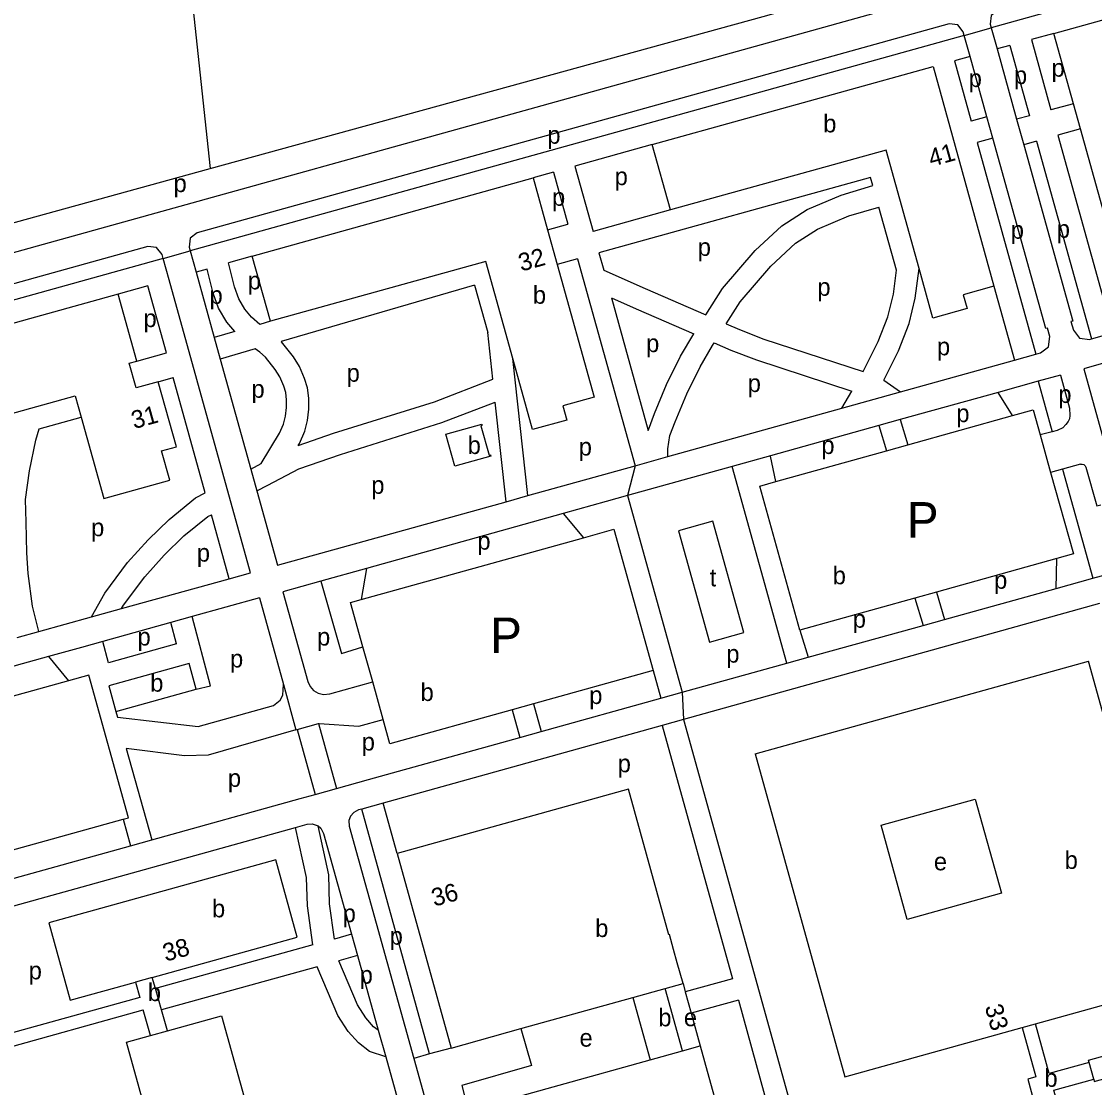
# Model space of a CAD drawing. Extents: x 158358 to 160383, y 379531 to 380764.
# Drawn here: x 159782.3 to 160024.2, y 380334.2 to 380574.3 of the extents above; entities that cross this region are included whole.
import ezdxf

# ---------------------------------------------------------------- set-up
doc = ezdxf.new("R2010")
doc.units = 0
for name, color, linetype in [('BLT_Basislijn', 7, 'Continuous'), ('BLT_Bebouwing', 7, 'Continuous'), ('BLT_Centroide', 7, 'Continuous'), ('BLT_Huisnummer', 7, 'Continuous'), ('BLT_Huisnummer_reeks', 7, 'Continuous'), ('BLT_Onderverdeling_panden', 7, 'Continuous'), ('BLT_Tekst_parkeren', 7, 'Continuous'), ('BLT_Vlakafsluiter', 7, 'Continuous')]:
    doc.layers.add(name, color=color, linetype=linetype)

msp = doc.modelspace()

# ---------------------------------------------------------------- linework, layer by layer
at = {"layer": 'BLT_Basislijn'}
for p, q in [((160019.45, 380555.77), (160014.34, 380554.39)), ((159999.92, 380552.86), (159996.4, 380551.89)), ((160009.51, 380553.09), (160006.62, 380552.32)), ((160021.02, 380550.12), (160015.93, 380548.69)), ((160001.26, 380548.05), (159997.73, 380547.07)), ((160011.11, 380547.33), (160008.23, 380546.52)), ((159902.25, 380540.36), (159905.49, 380528.69)), ((159907.07, 380541.71), (159911.15, 380527)), ((159928.62, 380531.85), (159911.15, 380527)), ((159900.88, 380527.41), (159905.49, 380528.69)), ((159912.48, 380522.19), (159913.57, 380518.27)), ((159907.67, 380520.85), (159920.6, 380474.22)), ((159884.45, 380514.89), (159840.82, 380502.26)), ((160001.52, 380514.71), (160006.16, 380498.01)), ((159915.29, 380512.06), (159923.59, 380482.15)), ((159838.46, 380506.78), (159836.06, 380506.08)), ((159830.39, 380504.44), (159825.74, 380503.1)), ((159888.54, 380493.7), (159887.4, 380504.22)), ((159808.28, 380497.8), (159814.96, 380499.67)), ((159835.01, 380500.57), (159827.08, 380498.28)), ((159896.41, 380467.5), (159893.06, 380498.43)), ((159813.13, 380493.16), (159816.51, 380494.1)), ((160005.7, 380485.55), (160002.44, 380490.76)), ((159891.53, 380466.14), (159889.1, 380488.56)), ((159975.59, 380483.29), (159977.26, 380477.62)), ((159980.4, 380484.63), (159982.08, 380478.96)), ((160014.64, 380481.89), (160011.94, 380481.16)), ((160015.78, 380482.21), (160014.64, 380481.89)), ((159952.38, 380470.67), (159951.13, 380476.36)), ((160016.98, 380473.47), (160014.29, 380472.73)), ((160021.01, 380474.58), (160016.98, 380473.47)), ((159918.9, 380467.52), (159931.22, 380423.2)), ((159904.41, 380463.48), (159908.96, 380458.01)), ((160015.55, 380446.6), (160015.72, 380453.35)), ((159860.05, 380451.09), (159858.84, 380444.08)), ((159983.71, 380444.42), (159985.53, 380438.27)), ((159988.53, 380445.77), (159990.35, 380439.61)), ((159957.78, 380437.19), (159959.65, 380431.09)), ((159788.36, 380431.24), (159792.9, 380425.76)), ((159924.67, 380428.11), (159926.4, 380421.86)), ((159897.69, 380420.61), (159899.45, 380414.37)), ((159803.6, 380418.88), (159803.97, 380417.56)), ((159892.88, 380419.27), (159894.63, 380413.03)), ((159931.55, 380417.09), (159964.23, 380299.3)), ((159844.46, 380414.81), (159848.51, 380400.21)), ((159849.28, 380416.16), (159853.32, 380401.55)), ((159926.73, 380415.75), (159942.56, 380358.68)), ((159805.92, 380410.57), (159811.68, 380389.98)), ((159866.96, 380386.87), (159863.8, 380398.24)), ((159805.2, 380394.59), (159806.87, 380388.64)), ((159856.72, 380368.69), (159852.83, 380367.61)), ((159847.96, 380366.27), (159812.51, 380356.46)), ((159858.06, 380363.87), (159853.83, 380362.7)), ((159848.97, 380361.36), (159813.87, 380351.65)), ((159931.43, 380357.59), (159931.94, 380355.74)), ((159942.56, 380358.68), (159931.94, 380355.74)), ((159931.94, 380355.74), (159933.28, 380350.92)), ((159943.9, 380353.87), (159933.28, 380350.92)), ((159943.9, 380353.87), (159956.78, 380307.42)), ((159933.28, 380350.92), (159935.32, 380343.57)), ((159879.13, 380343.06), (159874.31, 380341.72)), ((159874.31, 380341.72), (159870.73, 380340.69))]:
    msp.add_line(p, q, dxfattribs=at)
for points in [[(159789.02, 380665.27), (159793.46, 380660.92), (159804.18, 380646.64), (159811.39, 380635.41), (159815.6, 380624.35), (159817.77, 380612.72), (159819.82, 380588.21), (159824.85, 380541.18)], [(160152.18, 380625.57), (159545.87, 380457.04)], [(160140.65, 380615.31), (160002.48, 380576.9), (160000.91, 380575.68), (160000.67, 380573.7)], [(160141.65, 380612.04), (160000.9, 380572.88)], [(159824.85, 380541.18), (159949.46, 380575.46), (160033.92, 380599.61), (160042.54, 380602.05)], [(159994.6, 380572.01), (159993.38, 380573.58), (159991.4, 380573.82), (159821.88, 380526.7), (159820.31, 380525.47), (159820.07, 380523.5)], [(159994.83, 380571.19), (159994.6, 380572.01)], [(160000.67, 380573.7), (160000.9, 380572.88)], [(160000.9, 380572.88), (160002.22, 380568.14)], [(159994.83, 380571.19), (159820.31, 380522.63)], [(159996.15, 380566.45), (159994.83, 380571.19)], [(160015.04, 380571.62), (160009.94, 380570.24)], [(160009.94, 380570.24), (160014.34, 380554.39)], [(160005.11, 380568.92), (160002.22, 380568.14)], [(160002.22, 380568.14), (160006.62, 380552.32)], [(160005.11, 380568.92), (160009.51, 380553.09)], [(159996.15, 380566.45), (159992.63, 380565.48)], [(159992.63, 380565.48), (159996.4, 380551.89)], [(159999.92, 380552.86), (159996.15, 380566.45)], [(160001.26, 380548.05), (159999.92, 380552.86)], [(160006.62, 380552.32), (160008.23, 380546.52)], [(160010.98, 380499.34), (160012.02, 380499.64), (160013.83, 380501.05), (160014.11, 380503.33), (160013.57, 380505.26), (160013.19, 380505.15), (160001.26, 380548.05)], [(160015.93, 380548.69), (160028.3, 380504.16)], [(159924.5, 380546.57), (159907.07, 380541.71)], [(159997.73, 380547.07), (160010.98, 380499.34)], [(160008.23, 380546.52), (160019.26, 380506.84), (160018.87, 380506.73), (160019.41, 380504.8), (160020.82, 380502.99), (160023.1, 380502.71), (160023.49, 380502.82)], [(160011.11, 380547.33), (160023.49, 380502.82)], [(159748.71, 380520.22), (159824.85, 380541.18)], [(159902.25, 380540.36), (159897.64, 380539.08)], [(159974.24, 380537.33), (159973.72, 380539.18), (159912.48, 380522.19)], [(159936.54, 380508.23), (159940.31, 380514.16), (159947.65, 380522.7), (159953.71, 380528.31), (159959.38, 380531.99), (159967.11, 380535.22), (159974.24, 380537.33)], [(159941.18, 380506.2), (159944.34, 380511.18), (159951.25, 380519.22), (159956.79, 380524.35), (159961.72, 380527.55), (159968.79, 380530.51), (159975.58, 380532.52)], [(159979.54, 380518.27), (159975.58, 380532.52)], [(159814, 380521.81), (159812.77, 380523.38), (159810.8, 380523.62), (159592.76, 380463.02), (159590.81, 380462.27), (159589.15, 380461.15), (159588.02, 380459.94), (159587.63, 380459.39)], [(159820.07, 380523.5), (159820.31, 380522.63)], [(159814.24, 380520.94), (159814, 380521.81)], [(159820.31, 380522.63), (159821.65, 380517.81)], [(159834.31, 380521.48), (159828.96, 380519.93)], [(159814.24, 380520.94), (159586.57, 380457.59)], [(159815.58, 380516.12), (159814.24, 380520.94)], [(159836.06, 380506.08), (159834.19, 380507.69), (159832.67, 380509.48), (159831.28, 380511.86), (159830.33, 380514.55), (159828.96, 380519.93)], [(159907.67, 380520.85), (159903.05, 380519.57)], [(159976.66, 380493.51), (159979.98, 380500.15), (159982.39, 380506.3), (159983.77, 380511.99), (159984.63, 380518.64)], [(159824.15, 380518.54), (159821.65, 380517.81)], [(159821.65, 380517.81), (159825.74, 380503.1)], [(159830.39, 380504.44), (159828.58, 380506.58), (159826.72, 380509.74), (159825.54, 380513.1), (159824.15, 380518.54)], [(159913.57, 380518.27), (159922.91, 380514.19), (159936.54, 380508.23)], [(159972.06, 380495.49), (159972.11, 380495.58), (159975.41, 380502.19), (159977.62, 380507.81), (159978.85, 380512.9), (159979.54, 380518.27)], [(159810.76, 380514.78), (159804.07, 380512.92)], [(159814.96, 380499.67), (159810.76, 380514.78)], [(159833.92, 380450.13), (159815.58, 380516.12)], [(159884.45, 380514.89), (159887.4, 380504.22)], [(159915.29, 380512.06), (159920.9, 380509.61), (159933.83, 380503.96)], [(159941.18, 380506.2), (159944.14, 380504.91), (159949.65, 380502.78), (159972.06, 380495.49)], [(160023.49, 380502.82), (160028.3, 380504.16)], [(159825.74, 380503.1), (159827.08, 380498.28)], [(159844.66, 380478.79), (159844.95, 380479.26), (159846.15, 380482.03), (159846.74, 380484.45), (159847.08, 380487.01), (159847.06, 380489.44), (159846.76, 380491.77), (159846.13, 380493.87), (159844.98, 380496.56), (159843.61, 380498.79), (159840.95, 380502.14), (159840.82, 380502.26)], [(159923.59, 380482.15), (159923.62, 380482.36), (159924.98, 380485.98), (159927.71, 380492.51), (159930.87, 380498.89), (159933.83, 380503.96)], [(159928.03, 380476.29), (159927.97, 380478.02), (159928.48, 380481.06), (159929.63, 380484.14), (159932.26, 380490.44), (159935.27, 380496.51), (159938.07, 380501.32), (159938.47, 380501.93)], [(159938.47, 380501.93), (159942.23, 380500.29), (159947.97, 380498.06), (159969.49, 380491.07)], [(159836.32, 380474.71), (159840.5, 380481.57), (159841.39, 380483.62), (159841.82, 380485.37), (159842.08, 380487.32), (159842.06, 380489.1), (159841.86, 380490.72), (159841.42, 380492.15), (159840.52, 380494.26), (159839.51, 380495.92), (159837.31, 380498.68), (159836.05, 380499.79), (159835.01, 380500.57)], [(160006.16, 380498.01), (160010.98, 380499.34)], [(159827.08, 380498.28), (159833.97, 380473.48)], [(159980.47, 380490.87), (160006.16, 380498.01)], [(160028.8, 380498.07), (160021.81, 380496.07)], [(160016.49, 380494.66), (160011.47, 380493.27)], [(160016.49, 380494.66), (160018.58, 380487.18), (160018.65, 380485.56), (160018.51, 380484.83), (160018.24, 380484.21), (160017.75, 380483.49), (160017.01, 380482.81), (160015.78, 380482.21)], [(160021.81, 380496.07), (160027.37, 380476.05), (160027.97, 380474.83), (160028.49, 380474.26), (160029.15, 380473.74), (160029.64, 380473.49), (160030.2, 380473.3), (160030.98, 380473.15), (160032.36, 380473.3), (160060.95, 380481.22)], [(159823.73, 380468.14), (159816.51, 380494.1)], [(159844.66, 380478.79), (159852.67, 380481.54), (159875.42, 380488.66), (159888.54, 380493.7)], [(159976.66, 380493.51), (159980.47, 380490.87)], [(160011.47, 380493.27), (160002.44, 380490.76)], [(160011.47, 380493.27), (160014.64, 380481.89)], [(159967.25, 380487.19), (159969.49, 380491.07)], [(159967.25, 380487.19), (159980.47, 380490.87)], [(160002.44, 380490.76), (159980.4, 380484.63)], [(159835.34, 380468.56), (159837.84, 380469.86), (159844.86, 380473.57), (159854.23, 380476.79), (159877.06, 380483.94), (159889.1, 380488.56)], [(159928.03, 380476.29), (159967.25, 380487.19)], [(159786.28, 380482.56), (159795.74, 380485.19)], [(159786.18, 380436.86), (159784.81, 380442.59), (159783.8, 380449.97), (159783.49, 380454.65), (159783.33, 380461.52), (159783.24, 380466.64), (159784.08, 380473.1), (159785.51, 380479.98), (159786.28, 380482.56)], [(159975.59, 380483.29), (159951.11, 380476.48)], [(159980.4, 380484.63), (159975.59, 380483.29)], [(159920.6, 380474.22), (159928.03, 380476.29)], [(159951.11, 380476.48), (159942.51, 380474.09)], [(159833.97, 380473.48), (159836.32, 380474.71)], [(159833.97, 380473.48), (159835.34, 380468.56)], [(159896.41, 380467.5), (159920.6, 380474.22)], [(159942.51, 380474.09), (159918.9, 380467.52)], [(159954.83, 380429.75), (159942.51, 380474.09)], [(160016.98, 380473.47), (160023.81, 380448.89)], [(160021.01, 380474.58), (160021.43, 380474.61), (160021.79, 380474.49), (160022.09, 380474.23), (160022.25, 380473.9), (160024.68, 380465.19), (160025.57, 380465.43)], [(159798.12, 380440.18), (159801.08, 380445.56), (159806.22, 380452.41), (159810.87, 380457.55), (159815.6, 380462.15), (159821.54, 380467), (159823.73, 380468.14)], [(159835.34, 380468.56), (159839.99, 380451.82)], [(159839.99, 380451.82), (159891.53, 380466.14)], [(159891.53, 380466.14), (159896.41, 380467.5)], [(159914.08, 380466.18), (159904.41, 380463.48)], [(159918.9, 380467.52), (159914.08, 380466.18)], [(159804.85, 380442.05), (159805.29, 380442.84), (159810.08, 380449.22), (159814.47, 380454.08), (159818.93, 380458.41), (159824.31, 380462.8), (159825.1, 380463.21)], [(159829.11, 380448.79), (159825.1, 380463.21)], [(159904.41, 380463.48), (159860.05, 380451.09)], [(159860.05, 380451.09), (159849.78, 380448.22)], [(159804.85, 380442.05), (159829.11, 380448.79)], [(159829.11, 380448.79), (159833.92, 380450.13)], [(160015.55, 380446.6), (160023.81, 380448.89)], [(160023.81, 380448.89), (160029.69, 380450.52)], [(159849.78, 380448.22), (159841.24, 380445.83)], [(159849.78, 380448.22), (159854.45, 380431.97), (159859.27, 380433.44)], [(159990.35, 380439.61), (160015.55, 380446.6)], [(159835.92, 380444.47), (159820.81, 380440.26)], [(159835.92, 380444.47), (159841.33, 380424.94)], [(159841.24, 380445.83), (159846.84, 380425.64), (159847.34, 380424.53), (159848.16, 380423.62), (159849.2, 380423), (159850.38, 380422.7), (159851.78, 380422.85), (159861.47, 380425.54)], [(159798.12, 380440.18), (159804.85, 380442.05)], [(160025.27, 380443.18), (159931.55, 380417.09)], [(159786.18, 380436.86), (159798.12, 380440.18)], [(159815.99, 380438.92), (159800.66, 380434.66)], [(159820.81, 380440.26), (159815.99, 380438.92)], [(159817.27, 380434.09), (159815.99, 380438.92)], [(159821.67, 380423.9), (159824.93, 380424.65), (159820.81, 380440.26)], [(159985.53, 380438.27), (159990.35, 380439.61)], [(159781.36, 380435.52), (159786.18, 380436.86)], [(159959.65, 380431.09), (159985.53, 380438.27)], [(159800.66, 380434.66), (159795.84, 380433.32)], [(159801.94, 380429.81), (159800.66, 380434.66)], [(159817.27, 380434.09), (159801.94, 380429.81)], [(159795.84, 380433.32), (159788.36, 380431.24)], [(159788.36, 380431.24), (159707.73, 380408.83)], [(159931.22, 380423.2), (159954.83, 380429.75)], [(159954.83, 380429.75), (159959.65, 380431.09)], [(159803.97, 380417.56), (159822.14, 380415.49), (159839.08, 380420.24), (159840.61, 380421.4), (159841.22, 380422.54), (159841.33, 380424.94)], [(159841.33, 380424.94), (159844.17, 380414.72)], [(159899.45, 380414.37), (159926.4, 380421.86)], [(159926.4, 380421.86), (159931.22, 380423.2)], [(159849.28, 380416.16), (159849.39, 380416.19), (159858.33, 380415.59), (159863.81, 380417.09)], [(159931.55, 380417.09), (159926.73, 380415.75)], [(159844.17, 380414.72), (159824.37, 380409.04), (159819.03, 380408.88), (159805.92, 380410.57)], [(159844.17, 380414.72), (159844.46, 380414.81)], [(159844.46, 380414.81), (159849.28, 380416.16)], [(159926.73, 380415.75), (159863.8, 380398.24)], [(159860.52, 380403.55), (159894.63, 380413.03)], [(159894.63, 380413.03), (159899.45, 380414.37)], [(159853.32, 380401.55), (159860.52, 380403.55)], [(159845.09, 380399.26), (159848.51, 380400.21)], [(159848.51, 380400.21), (159853.32, 380401.55)], [(159811.68, 380389.98), (159845.09, 380399.26)], [(159863.8, 380398.24), (159858.99, 380396.9)], [(159858.99, 380396.9), (159858.27, 380396.7), (159857.22, 380396.13), (159856.46, 380395.28), (159856.11, 380394.31), (159856.19, 380393.01), (159870.73, 380340.69)], [(159874.31, 380341.72), (159858.99, 380396.9)], [(159844.1, 380392.76), (159846.71, 380393.49), (159847.84, 380393.56), (159848.99, 380393.21), (159849.15, 380393.08)], [(159849.15, 380393.08), (159849.77, 380392.57), (159850.41, 380391.4), (159856.72, 380368.69)], [(159852.83, 380367.61), (159851.77, 380375.51), (159851.55, 380382.1), (159849.15, 380393.08)], [(159779.25, 380374.73), (159844.1, 380392.76)], [(159847.96, 380366.27), (159846.79, 380375.09), (159846.57, 380381.47), (159844.1, 380392.76)], [(159720.05, 380364.51), (159806.87, 380388.64)], [(159806.87, 380388.64), (159811.68, 380389.98)], [(159856.72, 380368.69), (159858.06, 380363.87)], [(159858.06, 380363.87), (159862.73, 380347.08)], [(159864.4, 380341.04), (159860.78, 380342.28), (159858.26, 380344.2), (159855.96, 380346.82), (159853.59, 380350.38), (159848.97, 380361.36)], [(159862.73, 380347.08), (159861.69, 380347.87), (159859.94, 380349.87), (159858.01, 380352.76), (159853.83, 380362.7)], [(160022.94, 380339.83), (160022.8, 380340.34), (160056.55, 380349.72)], [(159862.73, 380347.08), (159864.4, 380341.04)], [(159894.88, 380347.44), (159897.28, 380339.12), (159881.55, 380334.6), (159883.03, 380328.99)], [(160024, 380336.04), (160024.14, 380335.53), (160057.89, 380344.91)], [(159864.4, 380341.04), (159877.04, 380295.57)], [(159870.73, 380340.69), (159874.63, 380326.66)]]:
    msp.add_lwpolyline(points, dxfattribs=at)
msp.add_lwpolyline([(159930.41, 380459.57), (159937.4, 380434.52), (159945.12, 380436.64), (159938.13, 380461.72)], close=True, dxfattribs=at)
at = {"layer": 'BLT_Bebouwing'}
for p, q in [((159982.08, 380478.96), (160005.7, 380485.55)), ((160011.94, 380481.16), (160014.29, 380472.73)), ((159952.38, 380470.67), (159977.26, 380477.62)), ((159977.26, 380477.62), (159982.08, 380478.96)), ((160015.72, 380453.35), (159988.53, 380445.77)), ((159983.71, 380444.42), (159957.78, 380437.19)), ((159988.53, 380445.77), (159983.71, 380444.42)), ((159930.13, 380362.28), (159929.3, 380365.26)), ((159812.51, 380356.46), (159811.79, 380358.97)), ((159813.87, 380351.65), (159812.51, 380356.46)), ((159920.12, 380354.45), (159924.03, 380340.42)), ((159931.3, 380342.45), (159927.39, 380356.47)), ((159775.8, 380342.21), (159809.75, 380351.7)), ((159815.22, 380346.91), (159813.87, 380351.65)), ((159937.28, 380336.53), (159939.47, 380328.65))]:
    msp.add_line(p, q, dxfattribs=at)
for points in [[(160015.04, 380571.62), (160070.73, 380587.12)], [(160019.45, 380555.77), (160015.04, 380571.62)], [(159924.5, 380546.57), (159987.81, 380564.15)], [(159987.81, 380564.15), (160001.52, 380514.71)], [(160021.02, 380550.12), (160019.45, 380555.77)], [(160040.01, 380544.56), (160046.95, 380519.63), (160030.76, 380515.13), (160021.02, 380550.12)], [(159928.62, 380531.85), (159924.5, 380546.57)], [(159984.63, 380518.64), (159977.2, 380545.33), (159928.62, 380531.85)], [(159834.31, 380521.48), (159897.64, 380539.08)], [(159897.64, 380539.08), (159900.88, 380527.41)], [(159900.88, 380527.41), (159903.05, 380519.57)], [(159838.46, 380506.78), (159834.31, 380521.48)], [(159893.06, 380498.43), (159886.99, 380520.25), (159838.46, 380506.78)], [(159903.05, 380519.57), (159911.36, 380489.66), (159904.36, 380487.7), (159905.24, 380484.53), (159897.53, 380482.38), (159893.06, 380498.43)], [(160001.52, 380514.71), (159994.58, 380512.76), (159995.45, 380509.64), (159987.73, 380507.49), (159984.63, 380518.64)], [(159804.07, 380512.92), (159737.61, 380494.43)], [(159808.28, 380497.8), (159804.07, 380512.92)], [(159813.13, 380493.16), (159808.13, 380491.76), (159806.59, 380497.33), (159808.28, 380497.8)], [(159737.61, 380494.43), (159741.68, 380479.78), (159744.9, 380480.68), (159746.05, 380476.57), (159794.4, 380490.01), (159795.74, 380485.19)], [(159795.74, 380485.19), (159800.84, 380466.88), (159815.72, 380471.02), (159813.9, 380477.57), (159817.21, 380478.49), (159813.13, 380493.16)], [(160005.7, 380485.55), (160010.35, 380486.85), (160011.94, 380481.16)], [(159879.97, 380474.16), (159877.97, 380481.35), (159886.09, 380483.61), (159886.17, 380483.34), (159885.88, 380483.26), (159887.73, 380476.61), (159888.01, 380476.69), (159888.09, 380476.42), (159879.97, 380474.16)], [(160014.29, 380472.73), (160019.42, 380454.38), (160015.72, 380453.35)], [(159957.78, 380437.19), (159948.73, 380469.65), (159952.38, 380470.67)], [(159908.96, 380458.01), (159915.82, 380459.92), (159924.67, 380428.11)], [(159858.84, 380444.08), (159908.96, 380458.01)], [(159859.27, 380433.44), (159856.49, 380443.43), (159858.84, 380444.08)], [(159861.47, 380425.54), (159859.27, 380433.44)], [(159821.67, 380423.9), (159820.07, 380429.67), (159801.99, 380424.63), (159803.6, 380418.88)], [(159947.68, 380409.33), (160022.85, 380430.21)], [(160010.88, 380348.51), (160040.63, 380356.77), (160026.61, 380407.38), (160029.01, 380408.05), (160022.85, 380430.21)], [(159806.39, 380394.92), (159797.49, 380427.03), (159792.9, 380425.76)], [(159924.67, 380428.11), (159897.69, 380420.61)], [(159792.9, 380425.76), (159736.28, 380410.08), (159745.17, 380377.97), (159805.2, 380394.59)], [(159863.81, 380417.09), (159861.47, 380425.54)], [(159803.6, 380418.88), (159821.67, 380423.9)], [(159897.69, 380420.61), (159892.88, 380419.27)], [(159892.88, 380419.27), (159865.34, 380411.61), (159863.81, 380417.09)], [(159947.68, 380409.33), (159967.93, 380336.58), (160007.88, 380347.68)], [(159929.3, 380365.26), (159928.38, 380368.6), (159928.22, 380368.56), (159919.12, 380401.36), (159866.96, 380386.87)], [(159981.97, 380372.02), (159976.07, 380393.23), (159997.28, 380399.14), (160003.18, 380377.91), (159981.97, 380372.02)], [(159805.2, 380394.59), (159806.39, 380394.92)], [(159866.96, 380386.87), (159879.13, 380343.06)], [(159839.64, 380385.47), (159788.49, 380371.27), (159793.3, 380353.83), (159807.97, 380357.9)], [(159811.79, 380358.97), (159844.45, 380368.03), (159839.64, 380385.47)], [(159931.43, 380357.59), (159930.13, 380362.28)], [(159807.97, 380357.9), (159808.95, 380354.44), (159775.01, 380345.06)], [(159927.39, 380356.47), (159931.43, 380357.59)], [(159894.88, 380347.44), (159920.12, 380354.45)], [(159811.38, 380345.86), (159809.75, 380351.7)], [(159815.22, 380346.91), (159827.42, 380350.28), (159841.63, 380299.07), (159871.39, 380307.31), (159872.07, 380304.87), (159872.74, 380304.9), (159873.33, 380304.67), (159873.74, 380304.29), (159873.99, 380303.78), (159874.03, 380303.11), (159873.84, 380302.58), (159873.44, 380302.12), (159872.91, 380301.85), (159873.51, 380299.39), (159843.83, 380291.16), (159852.83, 380258.71)], [(159879.13, 380343.06), (159894.88, 380347.44)], [(160007.88, 380347.68), (160010.96, 380336.55), (160009.16, 380336.05), (160010.67, 380330.52), (160012.49, 380331.02), (160017.17, 380314.03)], [(160022.94, 380339.83), (160013.97, 380337.33), (160010.88, 380348.51)], [(159831.33, 380253.11), (159806, 380344.38), (159811.38, 380345.86)], [(159931.3, 380342.45), (159935.32, 380343.57)], [(159935.32, 380343.57), (159937.28, 380336.53)], [(159883.03, 380328.99), (159924.03, 380340.42)], [(160024, 380336.04), (160022.94, 380339.83)], [(160020.18, 380314.87), (160015.02, 380333.53), (160024, 380336.04)]]:
    msp.add_lwpolyline(points, dxfattribs=at)
at = {"layer": 'BLT_Onderverdeling_panden'}
for p, q in [((159811.79, 380358.97), (159807.97, 380357.9)), ((159811.38, 380345.86), (159815.22, 380346.91)), ((160007.88, 380347.68), (160010.88, 380348.51))]:
    msp.add_line(p, q, dxfattribs=at)
for points in [[(159920.12, 380354.45), (159927.39, 380356.47)], [(159924.03, 380340.42), (159931.3, 380342.45)]]:
    msp.add_lwpolyline(points, dxfattribs=at)
at = {"layer": 'BLT_Vlakafsluiter'}
for p, q in [((159994.83, 380571.19), (160000.9, 380572.88)), ((159814.24, 380520.94), (159820.31, 380522.63)), ((159920.6, 380474.22), (159918.9, 380467.52)), ((159931.22, 380423.2), (159931.55, 380417.09))]:
    msp.add_line(p, q, dxfattribs=at)

# ---------------------------------------------------------------- texts
at = {"layer": 'BLT_Centroide'}
for s, p in [('p', (160014.49, 380561.88)), ('p', (159995.82, 380559.55)), ('p', (160006.02, 380560.21)), ('b', (159963.02, 380549.33)), ('p', (159900.84, 380546.77)), ('p', (159916.01, 380537.44)), ('p', (159816.58, 380535.88)), ('p', (159901.89, 380532.79)), ('p', (160005.31, 380525.37)), ('p', (160015.68, 380525.58)), ('p', (159934.75, 380521.5)), ('p', (159833.32, 380513.96)), ('p', (159824.69, 380510.69)), ('b', (159897.58, 380510.72)), ('p', (159961.71, 380512.51)), ('p', (159809.81, 380505.46)), ('p', (159923.11, 380499.83)), ('p', (159988.66, 380499.11)), ('p', (159855.6, 380493.16)), ('p', (159834.15, 380489.54)), ('p', (159946.01, 380490.84)), ('p', (160016.03, 380488.38)), ('p', (159993.03, 380484.06)), ('b', (159882.88, 380476.88)), ('p', (159962.61, 380476.88)), ('p', (159907.92, 380476.53)), ('p', (159861.15, 380467.9)), ('p', (159798, 380458.35)), ('p', (159885.07, 380455.33)), ('p', (159821.83, 380452.63)), ('b', (159965.17, 380447.53)), ('t', (159937.44, 380447.06)), ('p', (160001.55, 380446.52)), ('p', (159969.69, 380437.74)), ('p', (159808.46, 380433.73)), ('p', (159848.93, 380433.72)), ('p', (159829.31, 380428.79)), ('p', (159941.18, 380429.88)), ('b', (159811.32, 380423.34)), ('b', (159872.26, 380421.24)), ('p', (159910.28, 380420.56)), ('p', (159859.01, 380410.07)), ('p', (159916.7, 380405.18)), ('p', (159828.83, 380401.89)), ('e', (159987.97, 380383.09)), ('b', (160017.45, 380383.41)), ('b', (159825.25, 380372.5)), ('p', (159854.7, 380371.42)), ('b', (159911.63, 380368.06)), ('p', (159865.3, 380366.34)), ('p', (159783.93, 380358.53)), ('p', (159858.53, 380357.56)), ('b', (159810.79, 380353.63)), ('b', (159925.85, 380347.95)), ('e', (159931.61, 380347.98)), ('e', (159908.09, 380343.37)), ('b', (160012.9, 380334.32))]:
    msp.add_text(s, height=4, dxfattribs=at).set_placement(p)
at = {"layer": 'BLT_Huisnummer'}
for s, rotation, p in [('41', 15.5346, (159987.38, 380541.53)), ('32', 15.5476, (159894.96, 380517.95)), ('31', 15.5322, (159807.7, 380482.48))]:
    msp.add_text(s, height=4, rotation=rotation, dxfattribs=at).set_placement(p)
at = {"layer": 'BLT_Huisnummer_reeks'}
for s, rotation, p in [('36', 15.5264, (159875.36, 380374.89)), ('38', 15.5241, (159814.79, 380362.49)), ('33', 285.5546, (159999.42, 380352.37))]:
    msp.add_text(s, height=4, rotation=rotation, dxfattribs=at).set_placement(p)
at = {"layer": 'BLT_Tekst_parkeren'}
for p in [(159981.89, 380458.04), (159887.96, 380432.04)]:
    msp.add_text('P', height=8, dxfattribs=at).set_placement(p)

doc.saveas('drawing.dxf')
